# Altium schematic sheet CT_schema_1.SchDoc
size 511 x 485 mm
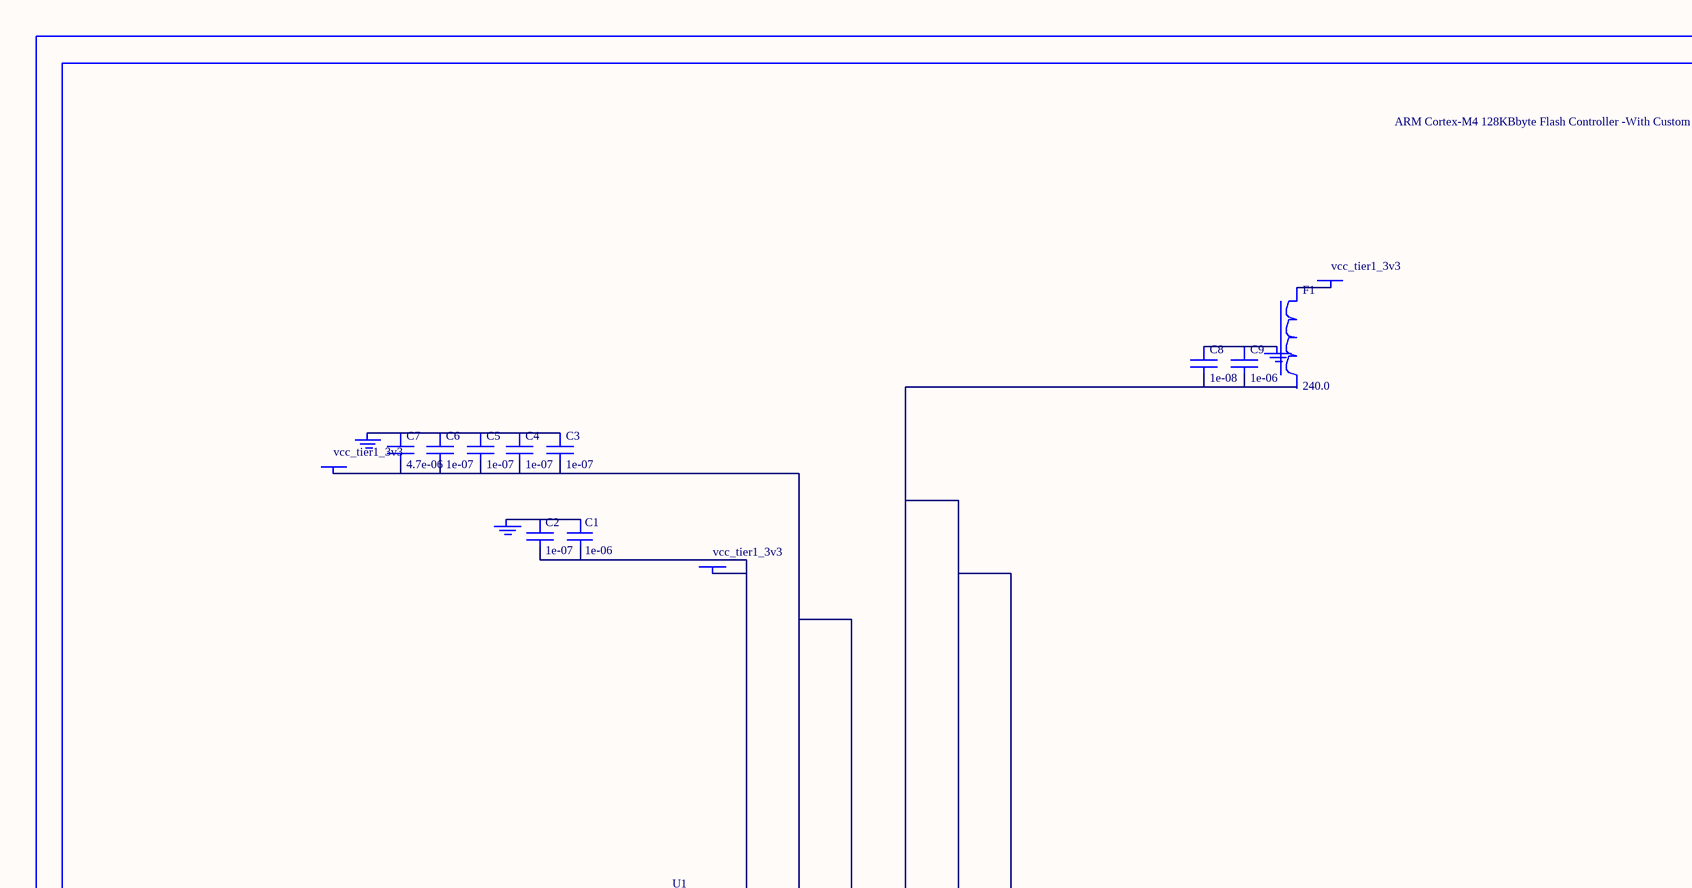
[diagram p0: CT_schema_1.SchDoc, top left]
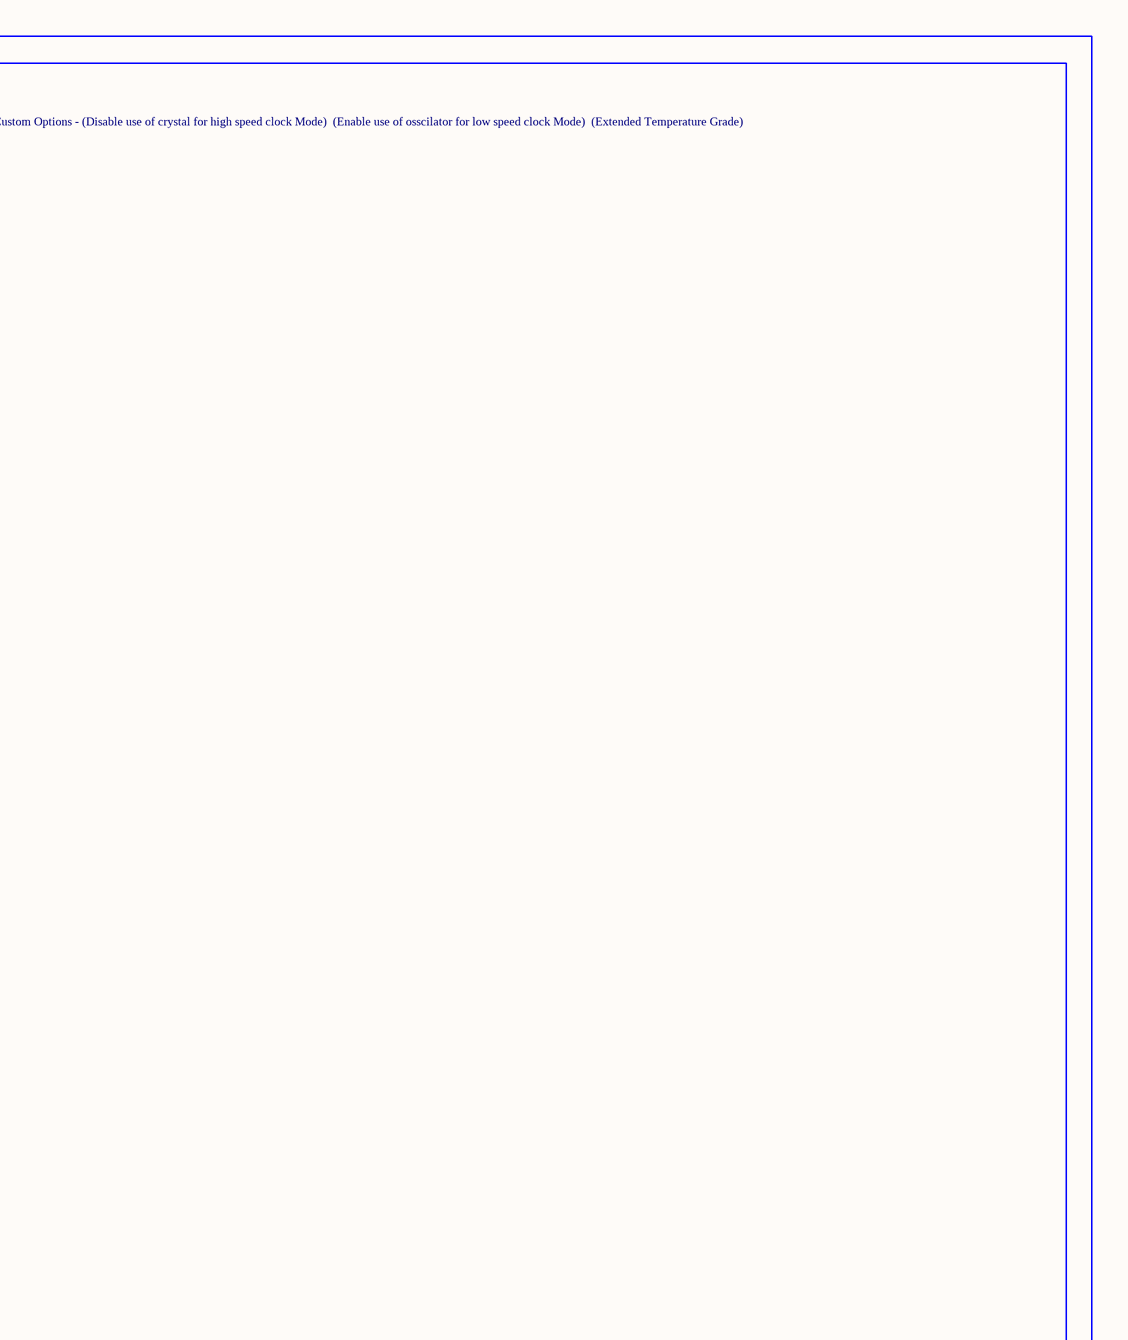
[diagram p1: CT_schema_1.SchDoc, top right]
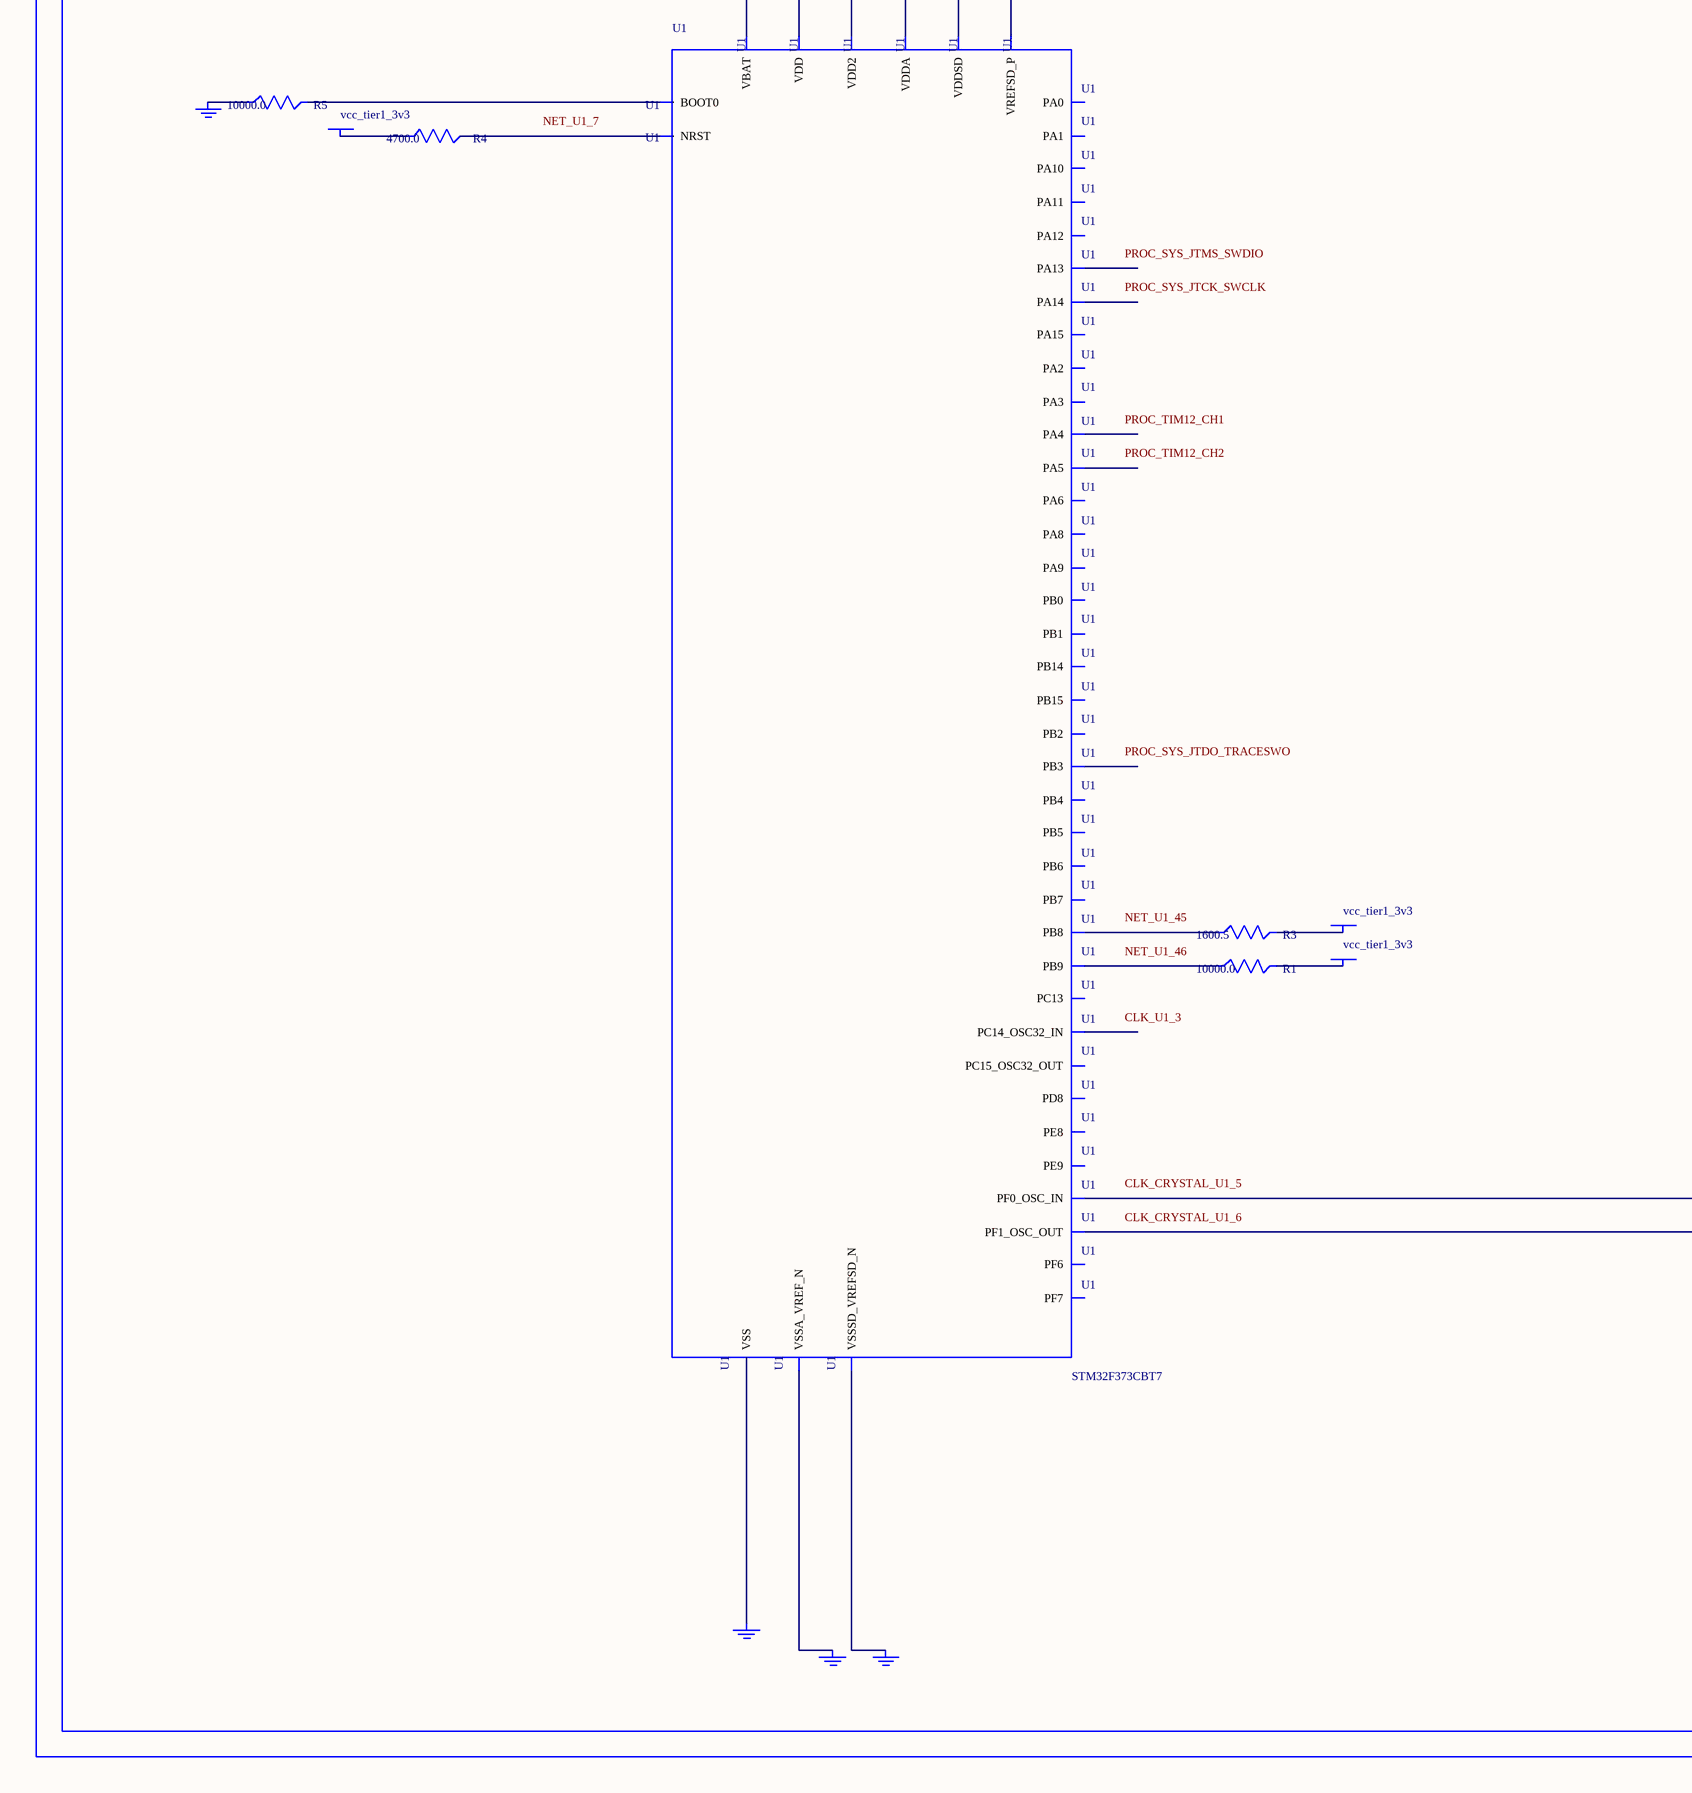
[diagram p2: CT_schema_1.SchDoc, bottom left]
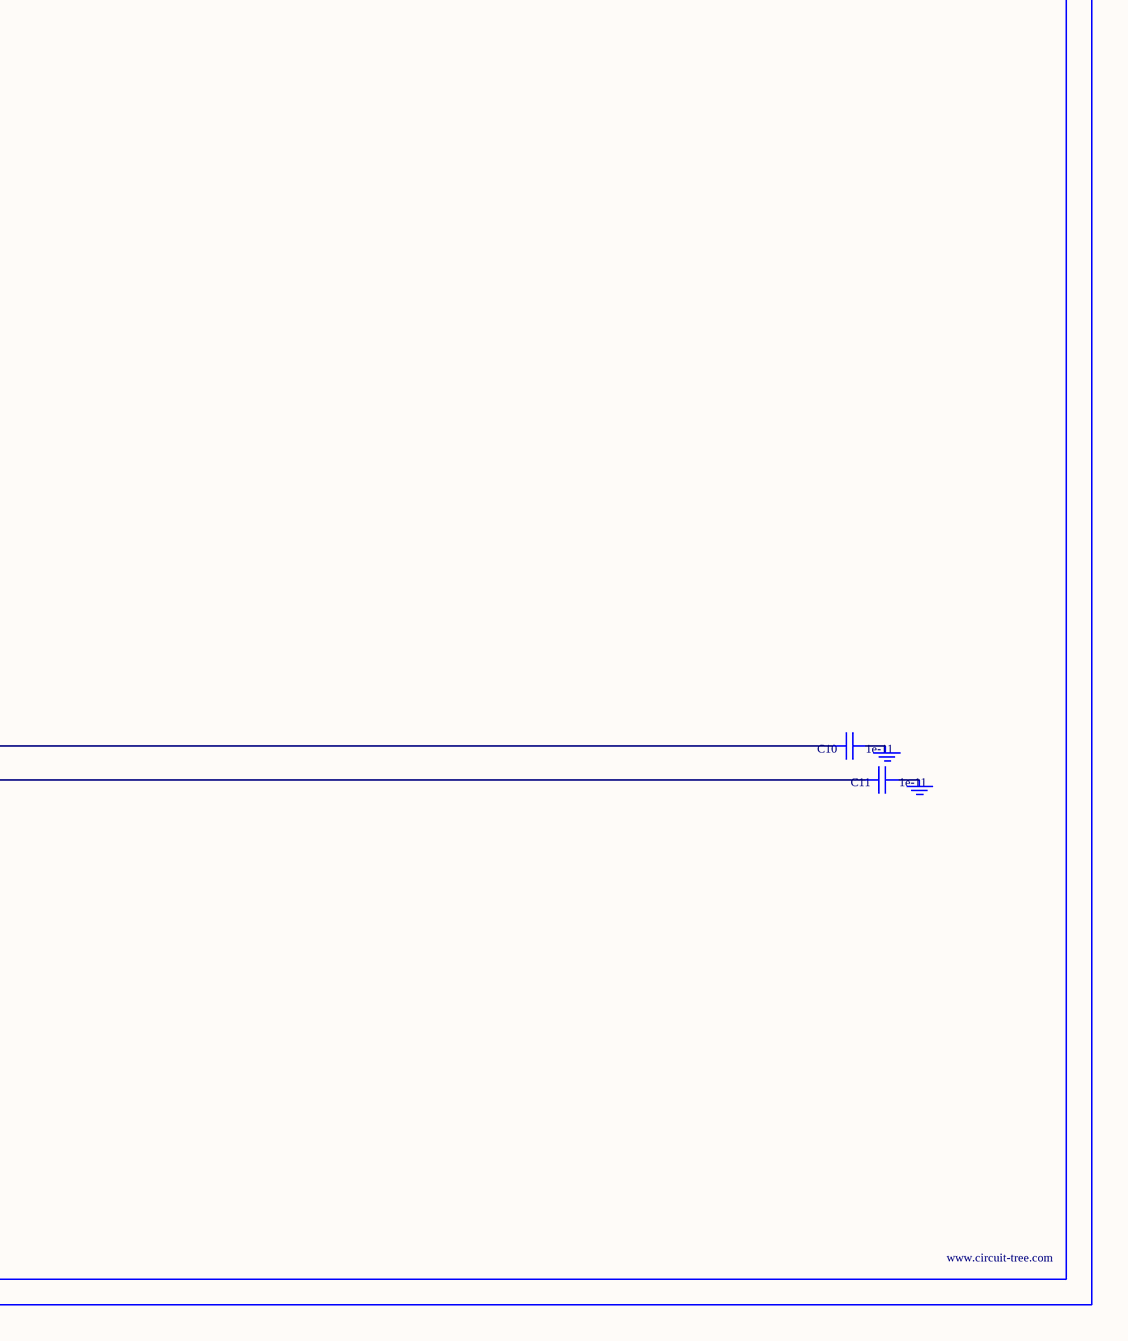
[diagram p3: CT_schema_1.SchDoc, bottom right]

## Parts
BORDER0  (no value)
C1  1e-06  [C0603]
C2  1e-07  [C0603]
C3  1e-07  [C0603]
C4  1e-07  [C0603]
C5  1e-07  [C0603]
C6  1e-07  [C0603]
C7  4.7e-06  [C0603]
C8  1e-08  [C0603]
C9  1e-06  [C0603]
C10  1e-11  [C0402]
C11  1e-11  [C0402]
F1  240.0  [L0603]
GND_INSTANCE_0_0  (no value)
GND_INSTANCE_0_1  (no value)
GND_INSTANCE_0_2  (no value)
GND_INSTANCE_0_3  (no value)
GND_INSTANCE_0_4  (no value)
GND_INSTANCE_0_5  (no value)
GND_INSTANCE_0_6  (no value)
GND_INSTANCE_0_7  (no value)
GND_INSTANCE_0_8  (no value)
POWER_INSTANCE_0_0  vcc_tier1_3v3
POWER_INSTANCE_0_1  vcc_tier1_3v3
POWER_INSTANCE_0_2  vcc_tier1_3v3
POWER_INSTANCE_0_3  vcc_tier1_3v3
POWER_INSTANCE_0_4  vcc_tier1_3v3
POWER_INSTANCE_0_5  vcc_tier1_3v3
R1  10000.0  [R0603]
R3  1600.5  [R0603]
R4  4700.0  [R0603]
R5  10000.0  [R0603]
U1  STM32F373CBT7  [LQFP48]

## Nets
NetC1_1: C1.1 C2.1 GND_INSTANCE_0_0.0(GND)
NetC1_2: C1.2 C2.2 POWER_INSTANCE_0_0.0(PWR) U1.1(VBAT)
NetC3_1: C3.1 C4.1 C5.1 C6.1 C7.1 GND_INSTANCE_0_5.0(GND)
NetC3_2: C3.2 C4.2 C5.2 C6.2 C7.2 POWER_INSTANCE_0_2.0(PWR) U1.17(VDD) U1.48(VDD2)
NetC8_1: C8.1 C9.1 GND_INSTANCE_0_4.0(GND)
NetC8_2: C8.2 C9.2 U1.9(VDDA) U1.24(VDDSD) U1.25(VREFSD_P)
NetC10_1: C10.1 GND_INSTANCE_0_1.0(GND)
NetC10_2: C10.2 U1.5(PF0_OSC_IN)
NetC11_1: C11.1 GND_INSTANCE_0_2.0(GND)
NetC11_2: C11.2 U1.6(PF1_OSC_OUT)
NetF1_1: F1.1 POWER_INSTANCE_0_1.0(PWR)
NetGND_INSTANCE_0_3_0: GND_INSTANCE_0_3.0(GND) U1.8(VSSA_VREF_N)
NetGND_INSTANCE_0_6_0: GND_INSTANCE_0_6.0(GND) U1.23(VSSSD_VREFSD_N)
NetGND_INSTANCE_0_7_0: GND_INSTANCE_0_7.0(GND) R5.1
NetGND_INSTANCE_0_8_0: GND_INSTANCE_0_8.0(GND) U1.47(VSS)
NetPOWER_INSTANCE_0_3_0: POWER_INSTANCE_0_3.0(PWR) R4.1
NetPOWER_INSTANCE_0_4_0: POWER_INSTANCE_0_4.0(PWR) R3.2
NetPOWER_INSTANCE_0_5_0: POWER_INSTANCE_0_5.0(PWR) R1.2
NetR1_1: R1.1 U1.46(PB9)
NetR3_1: R3.1 U1.45(PB8)
NetR4_2: R4.2 U1.7(NRST)
NetR5_2: R5.2 U1.44(BOOT0)

Not connected (* = marked no-connect by the designer): F1 2; U1 2(PC13) 3(PC14_OSC32_IN) 4(PC15_OSC32_OUT) 10(PA0) 11(PA1) 12(PA2) 13(PA3) 14(PA4) 15(PA5) 16(PA6) 18(PB0) 19(PB1) 20(PB2) 21(PE8) 22(PE9) 26(PB14) 27(PB15) 28(PD8) 29(PA8) 30(PA9) 31(PA10) 32(PA11) 33(PA12) 34(PA13) 35(PF6) 36(PF7) 37(PA14) 38(PA15) 39(PB3) 40(PB4) 41(PB5) 42(PB6) 43(PB7)

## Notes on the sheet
- Labels drawn without touching a wire or pin: CLK_CRYSTAL_U1_5, CLK_CRYSTAL_U1_6, CLK_U1_3, NET_U1_7, NET_U1_45, NET_U1_46, PROC_SYS_JTCK_SWCLK, PROC_SYS_JTDO_TRACESWO, PROC_SYS_JTMS_SWDIO, PROC_TIM12_CH1, PROC_TIM12_CH2

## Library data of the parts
BORDER0 = BORDER_PAGE0
C1 C9 = C0603C105K3RACTU
C2-C6 = 06035C104K4Z2A
C7 = GRM188R6YA475KE15D
C8 = 06035C103K4Z2A
C10 C11 = C0402C100K3GACTU
F1 = Z0603C241ASMST
GND_INSTANCE_0_0-GND_INSTANCE_0_8 = GND
POWER_INSTANCE_0_0-POWER_INSTANCE_0_5 = PWR
R1 R5 = RC0603JR-0710KL
R3 = R3
R4 = RC0603JR-074K7L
